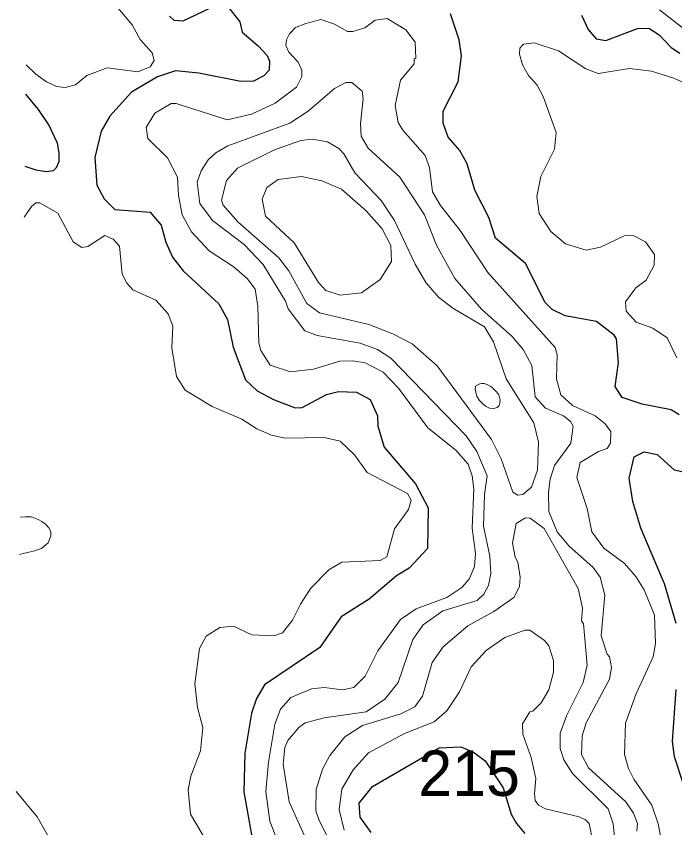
# Model space of a CAD drawing. Extents: x 673.6 to 698.9, y 7012 to 7040.1.
# Drawn here: x 673.888 to 675.045, y 7030.005 to 7031.432 of the extents above; entities that cross this region are included whole.
import ezdxf

# ---------------------------------------------------------------- set-up
doc = ezdxf.new("R2010")
doc.units = 0
doc.header["$LTSCALE"] = 0.032
doc.layers.add('1', color=7, linetype='Continuous', lineweight=25)
doc.layers.add('2', color=7, linetype='Continuous', lineweight=13)
doc.layers.add('21', color=7, linetype='Continuous')

msp = doc.modelspace()

# ---------------------------------------------------------------- linework, layer by layer
at = {"layer": '1'}
for points in [[(674.262, 7031.4466), (674.2812, 7031.422), (674.2853, 7031.4038), (674.3135, 7031.3799), (674.3291, 7031.3628), (674.3332, 7031.3528), (674.3325, 7031.3373), (674.323, 7031.3271), (674.305, 7031.318), (674.2831, 7031.317), (674.2089, 7031.3318), (674.1683, 7031.3358), (674.1362, 7031.3256), (674.0909, 7031.2986), (674.0526, 7031.2564), (674.0373, 7031.2298), (674.0261, 7031.1834), (674.0296, 7031.135), (674.0426, 7031.1108), (674.0615, 7031.092), (674.1237, 7031.0874), (674.1429, 7031.0646), (674.1513, 7031.0345), (674.1628, 7031.0085), (674.1817, 7030.9846), (674.244, 7030.9263), (674.2594, 7030.8987), (674.2695, 7030.8501), (674.2912, 7030.7929), (674.3118, 7030.7737), (674.3405, 7030.7583), (674.3781, 7030.7434), (674.3905, 7030.7443), (674.4333, 7030.7669), (674.4543, 7030.7721), (674.4859, 7030.7712), (674.5099, 7030.758), (674.5229, 7030.7292), (674.5233, 7030.7113), (674.5348, 7030.6744), (674.5897, 7030.6102), (674.6118, 7030.5675), (674.6106, 7030.4963), (674.5783, 7030.4616), (674.5566, 7030.4483), (674.5082, 7030.4074), (674.4592, 7030.376), (674.4218, 7030.3224), (674.3244, 7030.2568), (674.3103, 7030.2326), (674.3018, 7030.2067), (674.2899, 7030.1365), (674.2883, 7030.0684), (674.3014, 7029.9931)], [(674.1577, 7031.432), (674.1653, 7031.4247), (674.1817, 7031.424), (674.2283, 7031.4459)], [(675.0532, 7030.7312), (675.0387, 7030.7399), (674.988, 7030.75), (674.953, 7030.7616), (674.9407, 7030.7808), (674.9464, 7030.8235), (674.9431, 7030.8646), (674.9389, 7030.8715), (674.9078, 7030.8954), (674.8529, 7030.905), (674.8299, 7030.9165), (674.8173, 7030.9286), (674.7829, 7030.9972), (674.7303, 7031.042), (674.7188, 7031.0778), (674.6938, 7031.1264), (674.6806, 7031.1724), (674.6678, 7031.1961), (674.6472, 7031.2195), (674.6383, 7031.2438), (674.6386, 7031.2648), (674.6646, 7031.3165), (674.6703, 7031.3621), (674.6665, 7031.3901), (674.6514, 7031.4361)], [(674.8812, 7031.4339), (674.8933, 7031.4086), (674.9074, 7031.3922), (674.9243, 7031.3893), (674.9798, 7031.4105), (674.9994, 7031.4106), (675.0179, 7031.3991), (675.039, 7031.3768), (675.0542, 7031.3671)], [(673.9034, 7031.1683), (673.9228, 7031.162), (673.9414, 7031.159), (673.9537, 7031.1607), (673.9587, 7031.1662), (673.9634, 7031.1764), (673.9638, 7031.1916), (673.9609, 7031.2089), (673.9452, 7031.2407), (673.9274, 7031.2682), (673.913, 7031.2847), (673.9051, 7031.2948)], [(675.0475, 7030.3645), (675.0273, 7030.4343), (674.9859, 7030.5322), (674.9713, 7030.5789), (674.9654, 7030.6201), (674.9739, 7030.6577), (674.9916, 7030.666), (675.0143, 7030.6613), (675.044, 7030.6343), (675.0632, 7030.6304)], [(675.0605, 7030.0822), (675.045, 7030.1299), (675.041, 7030.1572), (675.0475, 7030.2486)], [(674.5121, 7029.9969), (674.4923, 7030.0242), (674.4906, 7030.0484), (674.5142, 7030.0777), (674.6314, 7030.1457), (674.6691, 7030.1476), (674.6917, 7030.1383), (674.712, 7030.1232), (674.7435, 7030.0754), (674.7579, 7030.0292), (674.7672, 7030.013), (674.7818, 7029.9954)]]:
    msp.add_lwpolyline(points, dxfattribs=at)
at = {"layer": '2'}
for points in [[(673.9058, 7031.3464), (673.9228, 7031.33), (673.9416, 7031.3166), (673.9592, 7031.3086), (673.9743, 7031.3063), (673.9923, 7031.3113), (674.0121, 7031.3276), (674.0479, 7031.3414), (674.1021, 7031.3343), (674.1238, 7031.3428), (674.1303, 7031.3542), (674.127, 7031.3678), (674.1062, 7031.3911), (674.0916, 7031.4167), (674.0576, 7031.458), (674.039, 7031.4678), (673.9848, 7031.4875), (673.9663, 7031.4978), (673.9154, 7031.5386), (673.9086, 7031.5489)], [(675.0185, 7031.4431), (675.0819, 7031.3937)], [(675.0256, 7029.9636), (675.0163, 7030.0125), (675.005, 7030.0451), (674.9732, 7030.0908), (674.9639, 7030.1095), (674.9572, 7030.134), (674.9588, 7030.1892), (674.977, 7030.2399), (675.0073, 7030.3061), (675.0114, 7030.3292), (675.0097, 7030.3794), (674.9916, 7030.4237), (674.9766, 7030.447), (674.9563, 7030.4705), (674.9208, 7030.497), (674.8998, 7030.5257), (674.8914, 7030.5664), (674.8734, 7030.621), (674.8791, 7030.6472), (674.9111, 7030.6669), (674.9265, 7030.6721), (674.9324, 7030.6817), (674.9329, 7030.702), (674.9232, 7030.7157), (674.9056, 7030.7292), (674.8656, 7030.7478), (674.8449, 7030.7662), (674.8376, 7030.7946), (674.8387, 7030.8367), (674.8352, 7030.8497), (674.717, 7030.9812), (674.6684, 7031.0551), (674.6337, 7031.0991), (674.6197, 7031.1231), (674.6145, 7031.1662), (674.6067, 7031.1868), (674.5672, 7031.2313), (674.5595, 7031.245), (674.5537, 7031.2747), (674.5634, 7031.3192), (674.5871, 7031.3483), (674.5876, 7031.3563), (674.5905, 7031.3584), (674.589, 7031.3865), (674.5725, 7031.4081), (674.5401, 7031.4279), (674.519, 7031.4248), (674.5006, 7031.4116), (674.4796, 7031.4049), (674.4704, 7031.405), (674.4476, 7031.418), (674.4235, 7031.4263), (674.3972, 7031.4192), (674.3786, 7031.4121), (674.3685, 7031.4011), (674.3632, 7031.3902), (674.3621, 7031.3803), (674.3669, 7031.3689), (674.3837, 7031.3514), (674.3901, 7031.3372), (674.39, 7031.3258), (674.3809, 7031.3071), (674.3432, 7031.2792), (674.3016, 7031.2596), (674.2587, 7031.2496), (674.1694, 7031.2783), (674.1604, 7031.2783), (674.1317, 7031.2614), (674.1165, 7031.236), (674.1193, 7031.2172), (674.1542, 7031.183), (674.1713, 7031.1492), (674.1732, 7031.1165), (674.1798, 7031.0827), (674.1959, 7031.0531), (674.2273, 7031.0195), (674.2709, 7030.9907), (674.2948, 7030.9701)], [(675.0991, 7031.2978), (675.0436, 7031.323), (675.0042, 7031.3352), (674.9656, 7031.34), (674.9106, 7031.331), (674.8891, 7031.3395), (674.8412, 7031.3711), (674.7984, 7031.3851), (674.7797, 7031.383), (674.7733, 7031.3756), (674.7723, 7031.3649), (674.7777, 7031.3465), (674.7885, 7031.3279), (674.8036, 7031.3108), (674.814, 7031.2909), (674.8366, 7031.2275), (674.8338, 7031.1982), (674.8102, 7031.1504), (674.8027, 7031.1152), (674.8072, 7031.085), (674.8274, 7031.0532), (674.8531, 7031.032), (674.8897, 7031.0204), (674.9146, 7031.0258), (674.9562, 7031.0458), (674.9719, 7031.0466), (674.9939, 7031.0353), (675.0095, 7031.0128), (675.0088, 7030.9941), (674.9952, 7030.9681), (674.9768, 7030.9545), (674.9588, 7030.9299), (674.9598, 7030.9137), (674.9774, 7030.8943), (675.0067, 7030.8838), (675.0318, 7030.8666), (675.049, 7030.8316)], [(674.9785, 7029.9992), (674.98, 7030.013), (674.9727, 7030.0309), (674.9594, 7030.0509), (674.8937, 7030.1107), (674.8816, 7030.1342), (674.8823, 7030.167), (674.8895, 7030.1896), (674.9305, 7030.2668), (674.9341, 7030.2873), (674.9308, 7030.3058), (674.9266, 7030.3107), (674.9161, 7030.3429), (674.9226, 7030.4143), (674.9139, 7030.4458), (674.902, 7030.4631), (674.859, 7030.5012), (674.8385, 7030.5258), (674.8241, 7030.5614), (674.8232, 7030.5953), (674.8261, 7030.6179), (674.8339, 7030.6422), (674.8624, 7030.6814), (674.8666, 7030.7112), (674.8621, 7030.7193), (674.8497, 7030.7294), (674.8183, 7030.7427), (674.8002, 7030.7627), (674.7943, 7030.8181), (674.779, 7030.8461), (674.7593, 7030.8688), (674.7055, 7030.9168), (674.6589, 7030.9708), (674.6264, 7031.0292), (674.6054, 7031.0828), (674.5621, 7031.1491), (674.5065, 7031.1999), (674.4945, 7031.2212), (674.4929, 7031.2433), (674.4977, 7031.2865), (674.4962, 7031.3), (674.478, 7031.3152), (674.4674, 7031.3153), (674.4476, 7031.3046), (674.4009, 7031.2651), (674.3688, 7031.2439), (674.2599, 7031.2042), (674.2391, 7031.192), (674.2257, 7031.1792), (674.2129, 7031.1604), (674.2061, 7031.1403), (674.2108, 7031.1025), (674.2329, 7031.0731), (674.2884, 7031.0307), (674.3218, 7030.9956), (674.3615, 7030.931), (674.3662, 7030.9173), (674.3953, 7030.8787), (674.4168, 7030.8707), (674.4927, 7030.8574), (674.5232, 7030.8461), (674.5465, 7030.8311), (674.6785, 7030.6946), (674.6976, 7030.6666), (674.7154, 7030.6239), (674.7107, 7030.5913), (674.709, 7030.5358), (674.7204, 7030.4828), (674.7222, 7030.4525), (674.718, 7030.4312), (674.7096, 7030.4163), (674.6979, 7030.4048), (674.6376, 7030.3866), (674.603, 7030.362), (674.5848, 7030.3364), (674.5594, 7030.261), (674.5361, 7030.2312), (674.5032, 7030.2092), (674.4291, 7030.1988), (674.3961, 7030.1898)], [(674.2191, 7029.9875), (674.1946, 7030.0296), (674.1905, 7030.072), (674.1951, 7030.096), (674.212, 7030.1405), (674.2159, 7030.1814), (674.2065, 7030.2167), (674.202, 7030.2582), (674.2104, 7030.3208), (674.2217, 7030.3423), (674.2459, 7030.3576), (674.2701, 7030.3596), (674.302, 7030.3444), (674.3407, 7030.3426), (674.3558, 7030.3483), (674.3738, 7030.3706), (674.3875, 7030.3985), (674.4061, 7030.4264), (674.4377, 7030.459), (674.4602, 7030.472), (674.5277, 7030.4755), (674.5392, 7030.4817), (674.5526, 7030.5307), (674.5776, 7030.5649), (674.5823, 7030.5813), (674.5758, 7030.5929), (674.5046, 7030.6297), (674.4825, 7030.6607), (674.4572, 7030.6851), (674.4295, 7030.6916), (674.361, 7030.69), (674.3365, 7030.6954), (674.3109, 7030.7066), (674.2846, 7030.7234), (674.2324, 7030.7458), (674.1849, 7030.7747), (674.1699, 7030.7985), (674.1617, 7030.8491), (674.1633, 7030.8873), (674.1549, 7030.9089), (674.1336, 7030.933), (674.093, 7030.9511), (674.0823, 7030.9628), (674.0744, 7030.9786), (674.0698, 7031.0279), (674.0588, 7031.0402), (674.0437, 7031.0466), (674.014, 7031.027), (674.0037, 7031.0254), (673.9884, 7031.0352), (673.9612, 7031.0858), (673.9296, 7031.1041), (673.9226, 7031.1039), (673.9148, 7031.0972), (673.9021, 7031.0785)], [(674.2948, 7030.9701), (674.3078, 7030.9519), (674.3128, 7030.9221), (674.3143, 7030.8571), (674.3179, 7030.8445), (674.3344, 7030.8188)], [(674.3344, 7030.8188), (674.3699, 7030.8067), (674.4104, 7030.8117), (674.4568, 7030.8254), (674.4795, 7030.8263), (674.5013, 7030.8228), (674.5328, 7030.806), (674.5598, 7030.7784), (674.6114, 7030.7086), (674.6607, 7030.6692), (674.6824, 7030.6448), (674.6893, 7030.6239), (674.6925, 7030.6012), (674.6893, 7030.5319), (674.6949, 7030.4875), (674.6933, 7030.4649), (674.6839, 7030.4425), (674.6714, 7030.4275), (674.6445, 7030.4104), (674.5906, 7030.39), (674.5633, 7030.3716), (674.5233, 7030.3163), (674.501, 7030.2719), (674.4816, 7030.2522), (674.4614, 7030.2479), (674.4294, 7030.2519), (674.4069, 7030.2496), (674.3708, 7030.2342), (674.3525, 7030.2141), (674.3427, 7030.1877), (674.3317, 7030.121), (674.327, 7030.0691), (674.334, 7030.0168), (674.347, 7029.9823)], [(673.894, 7030.4857), (673.9026, 7030.4882), (673.9184, 7030.4919), (673.9327, 7030.4963), (673.9404, 7030.5028), (673.9441, 7030.5065), (673.9475, 7030.5139), (673.9488, 7030.5179), (673.9491, 7030.526), (673.9457, 7030.5325), (673.9398, 7030.539), (673.933, 7030.5436), (673.9265, 7030.5473), (673.915, 7030.5517), (673.9036, 7030.552), (673.8949, 7030.5514)], [(674.4389, 7029.9826), (674.4202, 7030.0184), (674.4148, 7030.0355), (674.4149, 7030.0727), (674.4264, 7030.1086), (674.4391, 7030.1322), (674.4654, 7030.1654), (674.4966, 7030.1853), (674.5637, 7030.2057), (674.5886, 7030.2179), (674.6019, 7030.2366), (674.6191, 7030.2957), (674.6385, 7030.3237), (674.6816, 7030.3602), (674.7273, 7030.3853), (674.7625, 7030.4101), (674.7726, 7030.4293), (674.7738, 7030.446), (674.7698, 7030.4723), (674.7649, 7030.4812), (674.7599, 7030.5056), (674.7665, 7030.5403), (674.783, 7030.5501), (674.7911, 7030.5494), (674.8157, 7030.5313), (674.8754, 7030.4259), (674.883, 7030.3915), (674.8815, 7030.369), (674.8848, 7030.3639), (674.8912, 7030.2915), (674.8841, 7030.2607), (674.8559, 7030.2032), (674.8441, 7030.1718), (674.8437, 7030.1448), (674.8504, 7030.1246), (674.8655, 7030.101), (674.9283, 7030.0386), (674.9373, 7030.0122), (674.9406, 7029.9785)], [(674.9012, 7029.98), (674.8946, 7030.0128), (674.8887, 7030.0194), (674.8772, 7030.0249), (674.8179, 7030.039), (674.806, 7030.0452), (674.8001, 7030.0532), (674.7986, 7030.0649), (674.8009, 7030.0922), (674.7927, 7030.1292), (674.7785, 7030.1698), (674.778, 7030.1883), (674.7904, 7030.2094), (674.7956, 7030.2105), (674.8108, 7030.2249), (674.8239, 7030.2476), (674.8322, 7030.2792), (674.8323, 7030.2993), (674.8239, 7030.3251), (674.8162, 7030.3344), (674.7904, 7030.3529), (674.7816, 7030.353), (674.7467, 7030.3399), (674.7136, 7030.3173), (674.6874, 7030.2886), (674.667, 7030.2445), (674.6447, 7030.2108), (674.6227, 7030.1918), (674.5706, 7030.1713), (674.5071, 7030.1371), (674.48, 7030.1075), (674.46, 7030.0734), (674.4558, 7030.0377), (674.4641, 7030.0014)], [(674.3961, 7030.1898), (674.385, 7030.1819), (674.3654, 7030.1591), (674.3604, 7030.1464), (674.3573, 7030.1175), (674.3675, 7030.0511)], [(673.8882, 7030.0694), (673.9247, 7030.0246), (673.9544, 7029.9729)], [(674.3675, 7030.0511), (674.3968, 7029.9862), (674.5181, 7029.8422), (674.543, 7029.8036), (674.5564, 7029.7722), (674.5828, 7029.6918), (674.5964, 7029.676), (674.6309, 7029.6648), (674.6581, 7029.6663)]]:
    msp.add_lwpolyline(points, dxfattribs=at)
for points in [[(674.589, 7030.996), (674.553, 7031.0726), (674.5296, 7031.1077), (674.4832, 7031.1564), (674.4638, 7031.1899), (674.455, 7031.1994), (674.4352, 7031.2111), (674.409, 7031.2158), (674.3884, 7031.2134), (674.3421, 7031.1968), (674.2767, 7031.1649), (674.2577, 7031.1432), (674.2489, 7031.1087), (674.252, 7031.0996), (674.278, 7031.0701), (674.3496, 7031.0074), (674.3671, 7030.9841), (674.3988, 7030.9271), (674.421, 7030.9105), (674.5076, 7030.8902), (674.55, 7030.8736), (674.5837, 7030.8561), (674.628, 7030.8175), (674.7231, 7030.688), (674.74, 7030.6541), (674.7605, 7030.5951), (674.7697, 7030.5898), (674.7781, 7030.591), (674.7937, 7030.604), (674.8041, 7030.6338), (674.8059, 7030.683), (674.7976, 7030.7169), (674.7488, 7030.7944), (674.7269, 7030.8595), (674.7109, 7030.8858), (674.6552, 7030.9189), (674.6303, 7030.9379), (674.608, 7030.9639)], [(674.5478, 7031.001), (674.5462, 7031.029), (674.5312, 7031.0584), (674.5033, 7031.0896), (674.4596, 7031.1281), (674.4254, 7031.1425), (674.3892, 7031.1502), (674.3486, 7031.1447), (674.3283, 7031.1309), (674.3202, 7031.1102), (674.326, 7031.0803), (674.3764, 7031.0333), (674.4193, 7030.9638), (674.4324, 7030.9495), (674.4576, 7030.9415), (674.495, 7030.9456), (674.5279, 7030.9691)], [(674.7025, 7030.7857), (674.6954, 7030.7815), (674.6946, 7030.7761), (674.6956, 7030.7707), (674.6973, 7030.764), (674.7013, 7030.757), (674.7069, 7030.7518), (674.7127, 7030.7466), (674.7199, 7030.7431), (674.7274, 7030.7425), (674.733, 7030.744), (674.7366, 7030.7474), (674.738, 7030.7522), (674.7384, 7030.7576), (674.7374, 7030.7624), (674.7354, 7030.7676), (674.7302, 7030.7737), (674.7252, 7030.7789), (674.7207, 7030.7819), (674.7171, 7030.7839), (674.7105, 7030.7863), (674.7063, 7030.7865)]]:
    msp.add_lwpolyline(points, close=True, dxfattribs=at)

# ---------------------------------------------------------------- texts
at = {"layer": '21'}
msp.add_text('215', height=0.08, dxfattribs=at).set_placement((674.5947, 7030.0614))

doc.saveas('drawing.dxf')
